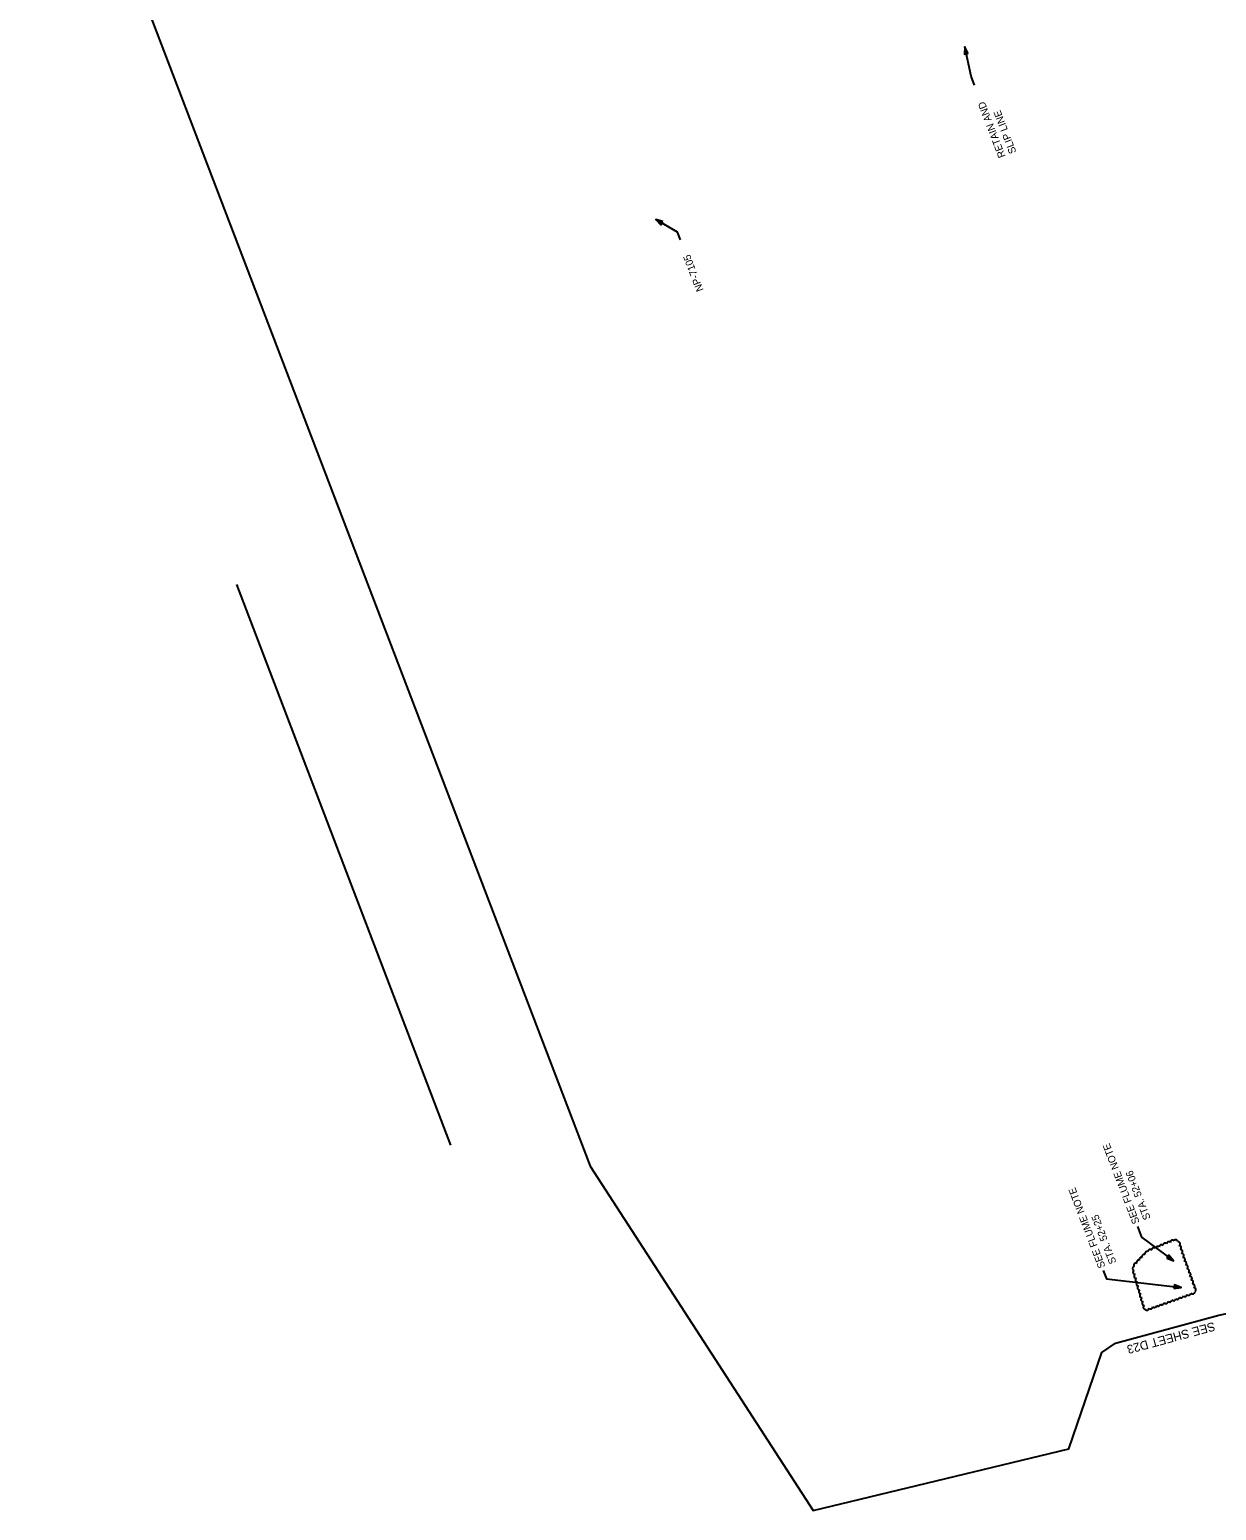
# Model space of a CAD drawing. Extents: x 1611058 to 1612754, y 1091411 to 1093437.
# Drawn here: x 1611114 to 1611925, y 1091411 to 1092422 of the extents above; entities that cross this region are included whole.
import ezdxf

# ---------------------------------------------------------------- set-up
doc = ezdxf.new("R2010")
doc.units = 0
for name, color, linetype in [('BR_CONCRETE', 7, 'Continuous'), ('Default', 7, 'Continuous'), ('RD_HY_Area_XP-Post sub TXT', 7, 'Continuous'), ('RD_HY_Misc', 7, 'Continuous')]:
    doc.layers.add(name, color=color, linetype=linetype)

msp = doc.modelspace()

# ---------------------------------------------------------------- linework, layer by layer
at = {"layer": 'BR_CONCRETE'}
for points in [[(1611755.1, 1092406.1), (1611752.8, 1092410.6), (1611752.5, 1092405.6)], [(1611546.5, 1092291.3), (1611541.7, 1092292.6), (1611545.3, 1092289.1)]]:
    msp.add_lwpolyline(points, close=True, dxfattribs=at)
for points in [[(1611759.5, 1092384.3), (1611757.1, 1092390.5), (1611752.8, 1092410.6)], [(1611558.6, 1092278.9), (1611556.6, 1092284), (1611541.7, 1092292.6)]]:
    msp.add_lwpolyline(points, dxfattribs=at)
for centre, start, end in [((1611894.6, 1091594.4), 40.2961, 185.2961), ((1611896.9, 1091594.6), 2.3864, 147.3864), ((1611875.2, 1091584.6), 64.2402, 209.2402), ((1611877.2, 1091586.6), 61.9184, 206.9184), ((1611879.3, 1091588), 40.2961, 185.2961), ((1611881.8, 1091589.1), 40.2961, 185.2961), ((1611884.4, 1091590.1), 40.2961, 185.2961), ((1611886.9, 1091591.2), 40.2961, 185.2961), ((1611889.5, 1091592.3), 40.2961, 185.2961), ((1611892, 1091593.3), 40.2961, 185.2961), ((1611898.4, 1091593.2), 305.1824, 90.1824), ((1611899.2, 1091590.5), 305.1824, 90.1824), ((1611900, 1091587.9), 305.1824, 90.1824), ((1611900.9, 1091585.3), 305.1824, 90.1824), ((1611868.7, 1091576.5), 108.1768, 253.1768), ((1611869.1, 1091573.9), 123.6657, 268.6657), ((1611869.6, 1091578.6), 64.2402, 209.2402), ((1611871.5, 1091580.6), 64.2402, 209.2402), ((1611873.3, 1091582.6), 64.2402, 209.2402), ((1611901.8, 1091582.6), 307.4374, 92.4374), ((1611902.7, 1091580), 307.4633, 92.4633), ((1611903.7, 1091577.4), 307.4633, 92.4633), ((1611904.6, 1091574.8), 307.4633, 92.4633), ((1611869.9, 1091571.2), 123.6657, 268.6657), ((1611870.7, 1091568.6), 123.6657, 268.6657), ((1611871.4, 1091565.9), 123.6657, 268.6657), ((1611905.6, 1091572.2), 307.4633, 92.4633), ((1611906.5, 1091569.6), 307.4633, 92.4633), ((1611907.4, 1091567), 307.4633, 92.4633), ((1611908.4, 1091564.4), 307.4633, 92.4633), ((1611872.2, 1091563.3), 123.6657, 268.6657), ((1611873, 1091560.6), 123.6657, 268.6657), ((1611873.7, 1091558), 123.6657, 268.6657), ((1611874.5, 1091555.3), 123.6657, 268.6657), ((1611892.8, 1091555), 217.1129, 2.1129), ((1611895.4, 1091555.9), 217.1129, 2.1129), ((1611898, 1091556.8), 217.1129, 2.1129), ((1611900.6, 1091557.8), 217.1129, 2.1129), ((1611903.2, 1091558.7), 217.1129, 2.1129), ((1611905.8, 1091559.6), 217.1129, 2.1129), ((1611908.4, 1091560.5), 217.1129, 2.1129), ((1611909.2, 1091561.9), 300.322, 85.322), ((1611875.3, 1091552.6), 123.6657, 268.6657), ((1611876.1, 1091550), 123.6657, 268.6657), ((1611877.2, 1091549.4), 217.1129, 2.1129), ((1611879.8, 1091550.3), 217.1129, 2.1129), ((1611882.4, 1091551.3), 217.1129, 2.1129), ((1611885, 1091552.2), 217.1129, 2.1129), ((1611887.6, 1091553.1), 217.1129, 2.1129), ((1611890.2, 1091554), 217.1129, 2.1129)]:
    msp.add_arc(centre, 1.45, start, end, dxfattribs=at)
at = {"layer": 'Default'}
for points in [[(1611870.7, 1091605.1), (1611873.5, 1091597.8), (1611895.3, 1091581.6)], [(1611847.3, 1091575), (1611849.5, 1091569.3), (1611900.5, 1091563.4)]]:
    msp.add_lwpolyline(points, dxfattribs=at)
for points in [[(1611890.7, 1091583.4), (1611895.3, 1091581.6), (1611892.2, 1091585.5)], [(1611895.6, 1091562.7), (1611900.5, 1091563.4), (1611895.9, 1091565.2)]]:
    msp.add_lwpolyline(points, close=True, dxfattribs=at)
at = {"layer": 'RD_HY_Misc'}
msp.add_line((1611401.8, 1091660.6), (1611255.6, 1092043.4), dxfattribs=at)
msp.add_lwpolyline([(1611114.1, 1092647.8), (1611496.9, 1091646.4), (1611649.2, 1091411.3), (1611823.9, 1091453.3), (1611846.4, 1091519), (1611855.6, 1091525.4), (1611926.2, 1091544.6), (1611937.1, 1091546.9), (1611940.3, 1091538.1), (1611975, 1091549.9), (1611978.7, 1091539.9), (1612061.7, 1091571.3), (1612067.6, 1091566.1), (1612138.1, 1091596.9), (1612153.4, 1091561), (1612277.2, 1091632.4), (1612477.1, 1091747.5), (1611951.2, 1093116.5)], dxfattribs=at)
msp.add_lwpolyline([(1611114.1, 1092647.8), (1611496.9, 1091646.4), (1611649.2, 1091411.3), (1611823.9, 1091453.3), (1611846.4, 1091519), (1611855.6, 1091525.4), (1611926.2, 1091544.6), (1611937.1, 1091546.9), (1611940.3, 1091538.1), (1611975, 1091549.9), (1611978.7, 1091539.9), (1612061.7, 1091571.3), (1612067.6, 1091566.1), (1612138.1, 1091596.9), (1612153.4, 1091561), (1612277.2, 1091632.4), (1612477.1, 1091747.5), (1611951.2, 1093116.5)], dxfattribs=at)

# ---------------------------------------------------------------- texts
at = {"layer": 'BR_CONCRETE'}
for s, p in [('RETAIN AND', (1611780.7, 1092335.9)), ('SLIP LINE', (1611788.1, 1092338.7)), ('NP-7105', (1611574.4, 1092244.6))]:
    msp.add_text(s, height=5, rotation=110.9145, dxfattribs=at).set_placement(p)
at = {"layer": 'Default'}
for s, p in [('SEE FLUME NOTE', (1611872.3, 1091607.9)), ('STA. 52+06', (1611879.8, 1091610.7)), ('SEE FLUME NOTE', (1611848.9, 1091577.8)), ('STA. 52+25', (1611856.4, 1091580.6))]:
    msp.add_text(s, height=5, rotation=110.9145, dxfattribs=at).set_placement(p)
at = {"layer": 'RD_HY_Area_XP-Post sub TXT'}
msp.add_text('SEE SHEET D23', height=6, rotation=195.1967, dxfattribs=at).set_placement((1611922.8, 1091540))

doc.saveas('drawing.dxf')
